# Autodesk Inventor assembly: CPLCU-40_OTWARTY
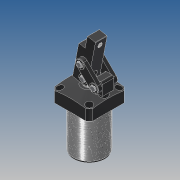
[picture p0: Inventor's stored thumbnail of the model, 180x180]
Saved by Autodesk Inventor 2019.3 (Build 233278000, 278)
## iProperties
Created: 2010-03
Part Number: CPLCU-40_OTWARTY
Material: Ogólny
Document SubType Name: Assembly
Designer: CADENGINEERING4
Sending System: PRO/ENGINEER BY PARAMETRIC TECHNOLOGY CORPORATION, 2007170
Preprocessor: PRO/ENGINEER BY PARAMETRIC TECHNOLOGY CORPORATION, 2007170
Title: CPLCU-40_ASM
Author: Administrator
Revision Number: 2LAST_VERSION
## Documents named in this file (10)
- E:\SERWER_ZAPAS\MODELE brakujace\PNEUMATIC\CPLCU(STEP)\cplcu-40_asm\CPLCU-40_OTWARTY.iam
- E:\SERWER_ZAPAS\MODELE brakujace\PNEUMATIC\CPLCU(STEP)\cplcu-40_asm\CPLCU-40-07.ipt
- E:\SERWER_ZAPAS\MODELE brakujace\PNEUMATIC\CPLCU(STEP)\cplcu-40_asm\CPLCU-40-05.ipt
- E:\SERWER_ZAPAS\MODELE brakujace\PNEUMATIC\CPLCU(STEP)\cplcu-40_asm\CPLCU-40-06.ipt
- E:\SERWER_ZAPAS\MODELE brakujace\PNEUMATIC\CPLCU(STEP)\cplcu-40_asm\CPLCU-40-01.ipt
- E:\SERWER_ZAPAS\MODELE brakujace\PNEUMATIC\CPLCU(STEP)\cplcu-40_asm\CPLCU-40-02.ipt
- E:\SERWER_ZAPAS\MODELE brakujace\PNEUMATIC\CPLCU(STEP)\cplcu-40_asm\CPLCU-40-08.ipt
- E:\SERWER_ZAPAS\MODELE brakujace\PNEUMATIC\CPLCU(STEP)\cplcu-40_asm\CPLCU-40-03.ipt
- E:\SERWER_ZAPAS\MODELE brakujace\PNEUMATIC\CPLCU(STEP)\cplcu-40_asm\CPLCU-40-04.ipt
- E:\SERWER_ZAPAS\MODELE brakujace\PNEUMATIC\CPLCU(STEP)\cplcu-40_asm\LHC01D-40-08.ipt
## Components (21 placed, 21 different names)
1. CPLCU-40-07_0 — Zestawiające:25, Zestawiające:26
2. CPLCU-40-05_1 — Zestawiające:1, Zestawiające:2
3. CPLCU-40-06_2 — Zestawiające:15, Równoległe:4, Zestawiające:20, Zestawiające:21, Zestawiające:25, Zestawiające:26
4. CPLCU-40-01_3 — Zestawiające:13, Zestawiające:14, Zestawiające:24
5. CPLCU-40-02_4 — Zestawiające:2, Zestawiające:3, Zestawiające:4
6. CPLCU-40-02_5 — Zestawiające:1, Zestawiające:3, Zestawiające:4, Zestawiające:5, Zestawiające:12, Zestawiające:14
7. CPLCU-40-08_6 — Zestawiające:17, Zestawiające:19, Zestawiające:21, Zestawiające:23
8. CPLCU-40-08_7 — Zestawiające:7, Zestawiające:11
9. CPLCU-40-08_8
10. CPLCU-40-08_9 — Zestawiające:16, Zestawiające:20, Zestawiające:22, Zestawiające:24
11. CPLCU-40-08_10 — Zestawiające:5
12. CPLCU-40-08_11 — Zestawiające:8, Zestawiające:9
13. CPLCU-40-03_12 — Zestawiające:15, Zestawiające:16, Zestawiające:17, Zestawiające:18, Równoległe:4
14. CPLCU-40-04_13 — Równoległe:1, Zestawiające:6, Zestawiające:7, Zestawiające:8, Zestawiające:10, Zestawiające:12, Zestawiające:13
15. CPLCU-40-04_14 — Równoległe:1
16. LHC01D-40-08_15 — Zestawiające:19, Zestawiające:23
17. LHC01D-40-08_16 — Zestawiające:18, Zestawiające:22
18. LHC01D-40-08_17 — Równoległe:3, Zestawiające:10, Zestawiające:11
19. LHC01D-40-08_18 — Równoległe:3
20. LHC01D-40-08_19 — Równoległe:2, Zestawiające:6, Zestawiające:9
21. LHC01D-40-08_20 — Równoległe:2
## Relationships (30: Mate 26, Flush 4)
- Równoległe:1 [Flush]: CPLCU-40-04_13 ↔ CPLCU-40-04_14
- Równoległe:2 [Flush]: LHC01D-40-08_19 ↔ LHC01D-40-08_20
- Równoległe:3 [Flush]: LHC01D-40-08_17 ↔ LHC01D-40-08_18
- Zestawiające:1 [Mate]: CPLCU-40-05_1 ↔ CPLCU-40-02_5
- Zestawiające:2 [Mate]: CPLCU-40-05_1 ↔ CPLCU-40-02_4
- Zestawiające:3 [Mate]: CPLCU-40-02_4 ↔ CPLCU-40-02_5
- Zestawiające:4 [Mate]: CPLCU-40-02_4 ↔ CPLCU-40-02_5
- Zestawiające:5 [Mate]: CPLCU-40-02_5 ↔ CPLCU-40-08_10
- Zestawiające:6 [Mate]: CPLCU-40-04_13 ↔ LHC01D-40-08_19
- Zestawiające:7 [Mate]: CPLCU-40-08_7 ↔ CPLCU-40-04_13
- Zestawiające:8 [Mate]: CPLCU-40-08_11 ↔ CPLCU-40-04_13
- Zestawiające:9 [Mate]: CPLCU-40-08_11 ↔ LHC01D-40-08_19
- Zestawiające:10 [Mate]: CPLCU-40-04_13 ↔ LHC01D-40-08_17
- Zestawiające:11 [Mate]: CPLCU-40-08_7 ↔ LHC01D-40-08_17
- Zestawiające:12 [Mate]: CPLCU-40-02_5 ↔ CPLCU-40-04_13
- Zestawiające:13 [Mate]: CPLCU-40-01_3 ↔ CPLCU-40-04_13
- Zestawiające:14 [Mate]: CPLCU-40-01_3 ↔ CPLCU-40-02_5
- Zestawiające:15 [Mate]: CPLCU-40-06_2 ↔ CPLCU-40-03_12
- Zestawiające:16 [Mate]: CPLCU-40-08_9 ↔ CPLCU-40-03_12
- Zestawiające:17 [Mate]: CPLCU-40-08_6 ↔ CPLCU-40-03_12
- Zestawiające:18 [Mate]: CPLCU-40-03_12 ↔ LHC01D-40-08_16
- Zestawiające:19 [Mate]: CPLCU-40-08_6 ↔ LHC01D-40-08_15
- Równoległe:4 [Flush]: CPLCU-40-06_2 ↔ CPLCU-40-03_12
- Zestawiające:20 [Mate]: CPLCU-40-06_2 ↔ CPLCU-40-08_9
- Zestawiające:21 [Mate]: CPLCU-40-06_2 ↔ CPLCU-40-08_6
- Zestawiające:22 [Mate]: CPLCU-40-08_9 ↔ LHC01D-40-08_16
- Zestawiające:23 [Mate]: CPLCU-40-08_6 ↔ LHC01D-40-08_15
- Zestawiające:24 [Mate]: CPLCU-40-01_3 ↔ CPLCU-40-08_9
- Zestawiające:25 [Mate]: CPLCU-40-07_0 ↔ CPLCU-40-06_2
- Zestawiające:26 [Mate]: CPLCU-40-07_0 ↔ CPLCU-40-06_2
